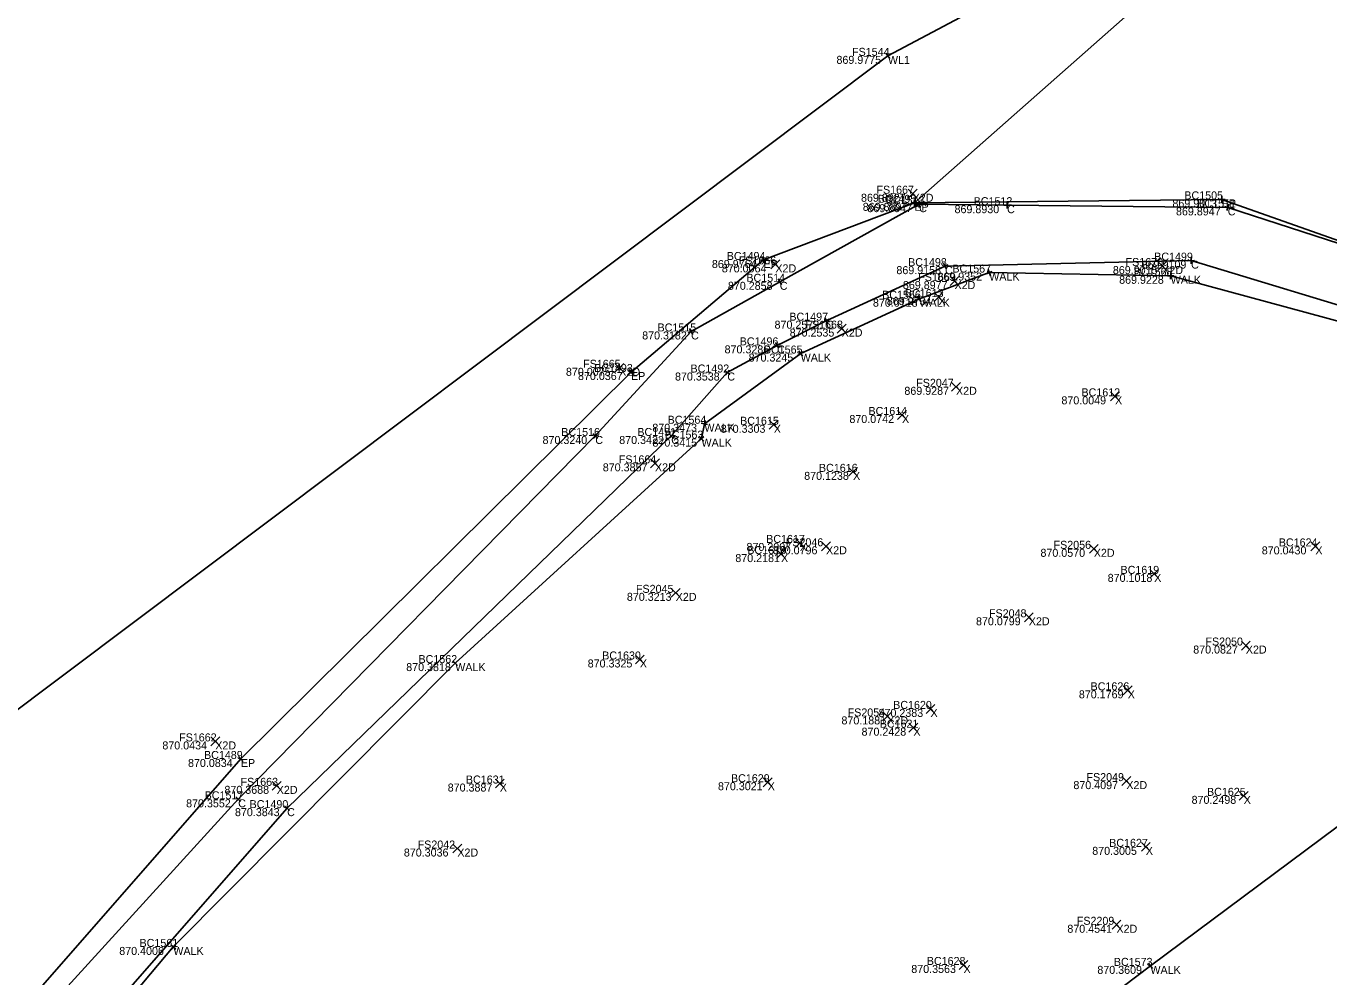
# Model space of a CAD drawing. Extents: x 1479425 to 1480294, y 379351 to 380102.
# Drawn here: x 1479701.41 to 1479711.18, y 379929 to 379936.13 of the extents above; entities that cross this region are included whole.
import ezdxf

# ---------------------------------------------------------------- set-up
doc = ezdxf.new("R2010")
doc.units = 0
for name, color, linetype in [('PV_X_Curb', 7, 'Continuous'), ('PV_X_EOP', 7, 'Continuous'), ('PV_X_Walk', 7, 'Continuous'), ('SV_X_Random_Point', 7, 'Continuous'), ('SV_X_Shot_Marker', 7, 'Continuous'), ('SV_X_Text_Comment', 7, 'Continuous'), ('SV_X_Text_Elevation', 7, 'Continuous'), ('SV_X_Text_Name', 7, 'Continuous'), ('UT_X_Water', 7, 'Continuous')]:
    doc.layers.add(name, color=color, linetype=linetype)

msp = doc.modelspace()

# ---------------------------------------------------------------- linework, layer by layer
at = {"layer": 'PV_X_Curb'}
for points in [[(1479696.2636, 379903.5386), (1479695.5705, 379906.7461), (1479695.2973, 379909.3412), (1479695.1738, 379911.6458), (1479695.3654, 379914.6115), (1479695.6976, 379917.6668), (1479696.2624, 379919.5688), (1479696.9758, 379921.5611), (1479698.1082, 379924.2136), (1479700.2799, 379927.5011), (1479703.0248, 379930.6372), (1479705.9498, 379933.539), (1479706.9435, 379934.3789), (1479708.0749, 379934.8076), (1479711.183, 379937.5526), (1479719.99, 379942.1167), (1479736.739, 379950.5318), (1479753.296, 379958.795), (1479766.716, 379965.5627), (1479785.836, 379974.8289), (1479802.25, 379983.0541), (1479831.407, 379997.252)], [(1479714.5618, 379931.5973), (1479714.9536, 379931.8464), (1479713.9233, 379933.1457), (1479712.2808, 379934.1691), (1479710.4236, 379934.7733), (1479708.7692, 379934.7899), (1479708.1103, 379934.7976), (1479707.0655, 379934.2154), (1479706.4002, 379933.8431), (1479705.6821, 379933.0592), (1479703.0049, 379930.3348), (1479700.4209, 379927.5017), (1479698.1162, 379923.7926), (1479697.0539, 379921.4468), (1479696.3167, 379919.5129), (1479695.8109, 379917.6805), (1479695.4613, 379914.2655), (1479695.2919, 379911.6604), (1479695.2827, 379911.4711), (1479695.5098, 379908.7638), (1479695.6518, 379906.8062)], [(1479696.7341, 379903.7226), (1479696.0777, 379906.871), (1479695.8572, 379909.3669), (1479695.6789, 379911.5748), (1479695.6301, 379911.7177), (1479695.7295, 379913.104), (1479695.9783, 379915.6746), (1479696.1977, 379917.4938), (1479696.6417, 379919.3847), (1479697.4123, 379921.3734), (1479698.5912, 379923.9386), (1479699.838, 379926.0575), (1479700.67, 379927.1843), (1479703.3721, 379930.2685), (1479706.2512, 379933.0593), (1479706.6718, 379933.5352), (1479707.0448, 379933.7387), (1479707.4133, 379933.9238), (1479708.304, 379934.3327), (1479710.1486, 379934.3742), (1479711.6155, 379933.9308), (1479713.6212, 379932.8847), (1479714.2993, 379932.0346), (1479714.5618, 379931.5973)]]:
    msp.add_lwpolyline(points, dxfattribs=at)
at = {"layer": 'PV_X_EOP'}
msp.add_lwpolyline([(1479708.0749, 379934.8076), (1479710.3785, 379934.8334), (1479712.1047, 379934.2215), (1479713.963, 379933.1704), (1479715.0883, 379931.8526)], dxfattribs=at)
at = {"layer": 'PV_X_Walk'}
msp.add_lwpolyline([(1479700.8191, 379927.2069), (1479702.5188, 379929.2278), (1479704.6321, 379931.3562), (1479706.478, 379933.0394), (1479706.4999, 379933.151), (1479707.2217, 379933.6773), (1479708.112, 379934.0884), (1479708.635, 379934.2846), (1479709.9955, 379934.2605), (1479711.7375, 379933.7876), (1479713.5401, 379932.634), (1479713.998, 379932.2143), (1479711.7035, 379930.4698), (1479709.8435, 379929.0857), (1479707.9993, 379927.6902), (1479707.5323, 379928.0023), (1479706.101, 379926.5176), (1479704.9058, 379925.0828), (1479704.4088, 379924.3811), (1479704.348, 379924.2805), (1479703.3879, 379922.6665), (1479702.6175, 379921.0036)], dxfattribs=at)
at = {"layer": 'SV_X_Random_Point'}
for p, q in [((1479708.0277, 379934.8423), (1479708.0943, 379934.9091)), ((1479708.0277, 379934.9091), (1479708.0943, 379934.8423)), ((1479706.9987, 379934.3127), (1479707.0653, 379934.3795)), ((1479706.9987, 379934.3795), (1479707.0653, 379934.3127)), ((1479709.8987, 379934.3), (1479709.9653, 379934.3668)), ((1479709.8987, 379934.3668), (1479709.9653, 379934.3)), ((1479708.3417, 379934.1876), (1479708.4083, 379934.2544)), ((1479708.3417, 379934.2544), (1479708.4083, 379934.1876)), ((1479708.2218, 379934.0676), (1479708.2884, 379934.1344)), ((1479708.2218, 379934.1344), (1479708.2884, 379934.0676)), ((1479707.4957, 379933.8311), (1479707.5623, 379933.8979)), ((1479707.4957, 379933.8979), (1479707.5623, 379933.8311)), ((1479705.8287, 379933.5371), (1479705.8953, 379933.6039)), ((1479705.8287, 379933.6039), (1479705.8953, 379933.5371)), ((1479708.3527, 379933.3945), (1479708.4193, 379933.4613)), ((1479708.3527, 379933.4613), (1479708.4193, 379933.3945)), ((1479709.5451, 379933.3231), (1479709.6117, 379933.3899)), ((1479709.5451, 379933.3899), (1479709.6117, 379933.3231)), ((1479707.9482, 379933.1834), (1479708.0148, 379933.2502)), ((1479707.9482, 379933.2502), (1479708.0148, 379933.1834)), ((1479706.9866, 379933.1099), (1479707.0532, 379933.1767)), ((1479706.9866, 379933.1767), (1479707.0532, 379933.1099)), ((1479706.0957, 379932.8206), (1479706.1623, 379932.8874)), ((1479706.0957, 379932.8874), (1479706.1623, 379932.8206)), ((1479707.5814, 379932.7568), (1479707.648, 379932.8236)), ((1479707.5814, 379932.8236), (1479707.648, 379932.7568)), ((1479707.1823, 379932.2238), (1479707.2489, 379932.2906)), ((1479707.1823, 379932.2906), (1479707.2489, 379932.2238)), ((1479707.3787, 379932.1988), (1479707.4453, 379932.2656)), ((1479707.3787, 379932.2656), (1479707.4453, 379932.1988)), ((1479711.0471, 379932.1979), (1479711.1137, 379932.2647)), ((1479711.0471, 379932.2647), (1479711.1137, 379932.1979)), ((1479707.0411, 379932.1403), (1479707.1077, 379932.2071)), ((1479707.0411, 379932.2071), (1479707.1077, 379932.1403)), ((1479709.3857, 379932.1797), (1479709.4523, 379932.2465)), ((1479709.3857, 379932.2465), (1479709.4523, 379932.1797)), ((1479709.8386, 379931.9918), (1479709.9052, 379932.0586)), ((1479709.8386, 379932.0586), (1479709.9052, 379931.9918)), ((1479706.2517, 379931.8496), (1479706.3183, 379931.9164)), ((1479706.2517, 379931.9164), (1479706.3183, 379931.8496)), ((1479708.8987, 379931.6664), (1479708.9653, 379931.7332)), ((1479708.8987, 379931.7332), (1479708.9653, 379931.6664)), ((1479710.5257, 379931.4543), (1479710.5923, 379931.5211)), ((1479710.5257, 379931.5211), (1479710.5923, 379931.4543)), ((1479705.9826, 379931.35), (1479706.0492, 379931.4168)), ((1479705.9826, 379931.4168), (1479706.0492, 379931.35)), ((1479709.6404, 379931.1186), (1479709.707, 379931.1854)), ((1479709.6404, 379931.1854), (1479709.707, 379931.1186)), ((1479707.8377, 379930.9229), (1479707.9043, 379930.9897)), ((1479707.8377, 379930.9897), (1479707.9043, 379930.9229)), ((1479708.1618, 379930.9792), (1479708.2284, 379931.046)), ((1479708.1618, 379931.046), (1479708.2284, 379930.9792)), ((1479708.0336, 379930.8383), (1479708.1002, 379930.9051)), ((1479708.0336, 379930.9051), (1479708.1002, 379930.8383)), ((1479702.7997, 379930.7355), (1479702.8663, 379930.8023)), ((1479702.7997, 379930.8023), (1479702.8663, 379930.7355)), ((1479706.9414, 379930.4294), (1479707.008, 379930.4962)), ((1479706.9414, 379930.4962), (1479707.008, 379930.4294)), ((1479709.6297, 379930.4378), (1479709.6963, 379930.5046)), ((1479709.6297, 379930.5046), (1479709.6963, 379930.4378)), ((1479703.2607, 379930.4024), (1479703.3273, 379930.4692)), ((1479703.2607, 379930.4692), (1479703.3273, 379930.4024)), ((1479704.9331, 379930.4196), (1479704.9997, 379930.4864)), ((1479704.9331, 379930.4864), (1479704.9997, 379930.4196)), ((1479710.5096, 379930.3273), (1479710.5762, 379930.3941)), ((1479710.5096, 379930.3941), (1479710.5762, 379930.3273)), ((1479709.7761, 379929.9449), (1479709.8427, 379930.0117)), ((1479709.7761, 379930.0117), (1479709.8427, 379929.9449)), ((1479704.6147, 379929.9323), (1479704.6813, 379929.9991)), ((1479704.6147, 379929.9991), (1479704.6813, 379929.9323)), ((1479709.5557, 379929.3605), (1479709.6223, 379929.4273)), ((1479709.5557, 379929.4273), (1479709.6223, 379929.3605)), ((1479708.4093, 379929.0592), (1479708.4759, 379929.126)), ((1479708.4093, 379929.126), (1479708.4759, 379929.0592))]:
    msp.add_line(p, q, dxfattribs=at)
at = {"layer": 'SV_X_Shot_Marker'}
for p, q in [((1479707.856, 379935.8947), (1479707.896, 379935.9247)), ((1479707.861, 379935.9297), (1479707.891, 379935.8897)), ((1479707.876, 379935.9097), (1479707.876, 379935.9097)), ((1479708.0499, 379934.8073), (1479708.0999, 379934.8079)), ((1479708.0746, 379934.8326), (1479708.0752, 379934.7826)), ((1479708.0749, 379934.8076), (1479708.0749, 379934.8076)), ((1479708.1353, 379934.7973), (1479708.0853, 379934.7979)), ((1479708.11, 379934.7726), (1479708.1106, 379934.8226)), ((1479708.1103, 379934.7976), (1479708.1103, 379934.7976)), ((1479708.7942, 379934.7896), (1479708.7442, 379934.7901)), ((1479708.7689, 379934.7649), (1479708.7694, 379934.8149)), ((1479708.7692, 379934.7899), (1479708.7692, 379934.7899)), ((1479710.3535, 379934.8331), (1479710.4035, 379934.8337)), ((1479710.3782, 379934.8584), (1479710.3788, 379934.8084)), ((1479710.3785, 379934.8334), (1479710.3785, 379934.8334)), ((1479710.4159, 379934.7495), (1479710.4313, 379934.7971)), ((1479710.4474, 379934.7656), (1479710.3998, 379934.7811)), ((1479710.4236, 379934.7733), (1479710.4236, 379934.7733)), ((1479706.9346, 379934.4023), (1479706.9524, 379934.3555)), ((1479710.148, 379934.3992), (1479710.1492, 379934.3492)), ((1479706.9201, 379934.3701), (1479706.9669, 379934.3878)), ((1479706.9435, 379934.3789), (1479706.9435, 379934.3789)), ((1479708.2813, 379934.3223), (1479708.3267, 379934.3431)), ((1479708.2936, 379934.3554), (1479708.3144, 379934.31)), ((1479708.304, 379934.3327), (1479708.304, 379934.3327)), ((1479708.6262, 379934.308), (1479708.6438, 379934.2612)), ((1479710.1236, 379934.3737), (1479710.1736, 379934.3748)), ((1479710.1486, 379934.3742), (1479710.1486, 379934.3742)), ((1479707.0873, 379934.2276), (1479707.0437, 379934.2033)), ((1479707.0777, 379934.1936), (1479707.0533, 379934.2373)), ((1479707.0655, 379934.2154), (1479707.0655, 379934.2154)), ((1479708.6116, 379934.2758), (1479708.6584, 379934.2934)), ((1479708.635, 379934.2846), (1479708.635, 379934.2846)), ((1479709.9705, 379934.261), (1479710.0205, 379934.2601)), ((1479709.9959, 379934.2855), (1479709.9951, 379934.2355)), ((1479709.9955, 379934.2605), (1479709.9955, 379934.2605)), ((1479708.1015, 379934.1111), (1479708.1225, 379934.0657)), ((1479708.0893, 379934.0779), (1479708.1347, 379934.0989)), ((1479708.112, 379934.0884), (1479708.112, 379934.0884)), ((1479707.391, 379933.9126), (1479707.4356, 379933.935)), ((1479707.4021, 379933.9462), (1479707.4245, 379933.9015)), ((1479707.4133, 379933.9238), (1479707.4133, 379933.9238)), ((1479706.422, 379933.8553), (1479706.3784, 379933.8309)), ((1479706.4124, 379933.8213), (1479706.388, 379933.8649)), ((1479706.4002, 379933.8431), (1479706.4002, 379933.8431)), ((1479707.0229, 379933.7267), (1479707.0667, 379933.7507)), ((1479707.0328, 379933.7607), (1479707.0568, 379933.7168)), ((1479707.0448, 379933.7387), (1479707.0448, 379933.7387)), ((1479707.2015, 379933.6626), (1479707.2419, 379933.692)), ((1479707.207, 379933.6975), (1479707.2364, 379933.6571)), ((1479707.2217, 379933.6773), (1479707.2217, 379933.6773)), ((1479705.9307, 379933.5229), (1479705.9689, 379933.5552)), ((1479705.9337, 379933.5581), (1479705.9659, 379933.5199)), ((1479705.9498, 379933.539), (1479705.9498, 379933.539)), ((1479706.6531, 379933.5518), (1479706.6905, 379933.5187)), ((1479706.6552, 379933.5165), (1479706.6884, 379933.554)), ((1479706.6718, 379933.5352), (1479706.6718, 379933.5352)), ((1479706.4754, 379933.1558), (1479706.5244, 379933.1462)), ((1479706.4951, 379933.1265), (1479706.5047, 379933.1756)), ((1479706.4999, 379933.151), (1479706.4999, 379933.151)), ((1479705.7005, 379933.0423), (1479705.6637, 379933.0761)), ((1479705.699, 379933.0777), (1479705.6652, 379933.0408)), ((1479705.6821, 379933.0592), (1479705.6821, 379933.0592)), ((1479706.2332, 379933.0419), (1479706.2691, 379933.0767)), ((1479706.2338, 379933.0773), (1479706.2686, 379933.0414)), ((1479706.2512, 379933.0593), (1479706.2512, 379933.0593)), ((1479706.4595, 379933.0226), (1479706.4965, 379933.0563)), ((1479706.4612, 379933.0579), (1479706.4948, 379933.0209)), ((1479706.478, 379933.0394), (1479706.478, 379933.0394)), ((1479704.6144, 379931.3738), (1479704.6498, 379931.3386)), ((1479704.6145, 379931.3385), (1479704.6497, 379931.374)), ((1479704.6321, 379931.3562), (1479704.6321, 379931.3562)), ((1479703.007, 379930.6196), (1479703.0425, 379930.6548)), ((1479703.0072, 379930.655), (1479703.0424, 379930.6195)), ((1479703.0248, 379930.6372), (1479703.0248, 379930.6372)), ((1479703.0227, 379930.3173), (1479702.9871, 379930.3523)), ((1479703.0224, 379930.3527), (1479702.9874, 379930.317)), ((1479703.0049, 379930.3348), (1479703.0049, 379930.3348)), ((1479703.3533, 379930.285), (1479703.3909, 379930.252)), ((1479703.3556, 379930.2497), (1479703.3886, 379930.2873)), ((1479703.3721, 379930.2685), (1479703.3721, 379930.2685)), ((1479702.4997, 379929.2439), (1479702.5379, 379929.2117)), ((1479702.5027, 379929.2087), (1479702.5349, 379929.247)), ((1479702.5188, 379929.2278), (1479702.5188, 379929.2278)), ((1479709.8636, 379929.1006), (1479709.8234, 379929.0708)), ((1479709.8584, 379929.0657), (1479709.8286, 379929.1058)), ((1479709.8435, 379929.0857), (1479709.8435, 379929.0857))]:
    msp.add_line(p, q, dxfattribs=at)
at = {"layer": 'UT_X_Water'}
msp.add_lwpolyline([(1479653.917, 379883.0752), (1479656.453, 379885.9011), (1479682.649, 379913.5823), (1479686.182, 379917.14), (1479686.736, 379917.6555), (1479692.788, 379923.2684), (1479699.703, 379929.7704), (1479707.876, 379935.9097), (1479714.6, 379939.4878), (1479720.618, 379942.7923), (1479734.686, 379951.003), (1479759.021, 379964.6195), (1479771.505, 379971.3041), (1479799.27, 379984.8376)], dxfattribs=at)

# ---------------------------------------------------------------- texts
at = {"layer": 'SV_X_Text_Comment'}
for s, p in [('WL1', (1479707.876, 379935.8497)), ('X2D', (1479708.061, 379934.8157)), ('EP', (1479708.0749, 379934.7476)), ('C', (1479708.1103, 379934.7376)), ('C', (1479708.7692, 379934.7299)), ('EP', (1479710.3785, 379934.7734)), ('C', (1479710.4236, 379934.7133)), ('EP', (1479706.9435, 379934.3189)), ('X2D', (1479707.032, 379934.2861)), ('C', (1479708.304, 379934.2727)), ('X2D', (1479709.932, 379934.2734)), ('C', (1479710.1486, 379934.3142)), ('C', (1479707.0655, 379934.1554)), ('X2D', (1479708.375, 379934.161)), ('WALK', (1479708.635, 379934.2246)), ('WALK', (1479709.9955, 379934.2005)), ('WALK', (1479708.112, 379934.0284)), ('X', (1479708.2551, 379934.041)), ('C', (1479707.4133, 379933.8638)), ('C', (1479706.4002, 379933.7831)), ('X2D', (1479707.529, 379933.8045)), ('C', (1479707.0448, 379933.6787)), ('WALK', (1479707.2217, 379933.6173)), ('X2D', (1479705.862, 379933.5105)), ('EP', (1479705.9498, 379933.479)), ('C', (1479706.6718, 379933.4752)), ('X2D', (1479708.386, 379933.3679)), ('X', (1479709.5784, 379933.2965)), ('WALK', (1479706.4999, 379933.091)), ('X', (1479707.0199, 379933.0833)), ('X', (1479707.9815, 379933.1568)), ('C', (1479705.6821, 379932.9992)), ('C', (1479706.2512, 379932.9993)), ('WALK', (1479706.478, 379932.9794)), ('X2D', (1479706.129, 379932.794)), ('X', (1479707.6147, 379932.7302)), ('X', (1479707.2156, 379932.1972)), ('X', (1479707.0744, 379932.1137)), ('X2D', (1479707.412, 379932.1722)), ('X2D', (1479709.419, 379932.1531)), ('X', (1479711.0804, 379932.1713)), ('X', (1479709.8719, 379931.9652)), ('X2D', (1479706.285, 379931.823)), ('X2D', (1479708.932, 379931.6398)), ('X2D', (1479710.559, 379931.4277)), ('X', (1479706.0159, 379931.3234)), ('WALK', (1479704.6321, 379931.2962)), ('X', (1479709.6737, 379931.092)), ('X', (1479708.1951, 379930.9526)), ('X2D', (1479707.871, 379930.8963)), ('X', (1479708.0669, 379930.8117)), ('X2D', (1479702.833, 379930.7089)), ('EP', (1479703.0248, 379930.5772)), ('X2D', (1479703.294, 379930.3758)), ('X', (1479704.9664, 379930.393)), ('X', (1479706.9747, 379930.4028)), ('X2D', (1479709.663, 379930.4112)), ('C', (1479703.0049, 379930.2748)), ('X', (1479710.5429, 379930.3007)), ('C', (1479703.3721, 379930.2085)), ('X2D', (1479704.648, 379929.9057)), ('X', (1479709.8094, 379929.9183)), ('X2D', (1479709.589, 379929.3339)), ('WALK', (1479702.5188, 379929.1678)), ('X', (1479708.4426, 379929.0326)), ('WALK', (1479709.8435, 379929.0257))]:
    msp.add_text(s, height=0.06, dxfattribs=at).set_placement(p)
at = {"layer": 'SV_X_Text_Elevation'}
for s, p in [('869.9775', (1479707.49, 379935.8497)), ('869.8927', (1479707.6741, 379934.8157)), ('869.8897', (1479707.687, 379934.7476)), ('869.8947', (1479707.722, 379934.7376)), ('869.8930', (1479708.3752, 379934.7299)), ('869.9013', (1479710.0086, 379934.7734)), ('869.8947', (1479710.0353, 379934.7133)), ('869.9764', (1479706.5561, 379934.3189)), ('870.0064', (1479706.6304, 379934.2861)), ('869.9158', (1479707.9393, 379934.2727)), ('869.9015', (1479709.5621, 379934.2734)), ('869.9109', (1479709.7783, 379934.3142)), ('870.2858', (1479706.6762, 379934.1554)), ('869.8977', (1479707.9881, 379934.161)), ('869.9352', (1479708.2467, 379934.2246)), ('869.9228', (1479709.6091, 379934.2005)), ('870.0118', (1479707.7634, 379934.0284)), ('869.9734', (1479707.8677, 379934.041)), ('870.2572', (1479707.0259, 379933.8638)), ('870.3182', (1479706.0336, 379933.7831)), ('870.2535', (1479707.1393, 379933.8045)), ('870.3286', (1479706.6513, 379933.6787)), ('870.3245', (1479706.8315, 379933.6173)), ('870.0075', (1479705.4619, 379933.5105)), ('870.0367', (1479705.5525, 379933.479)), ('870.3538', (1479706.2797, 379933.4752)), ('869.9287', (1479707.9991, 379933.3679)), ('870.0049', (1479709.1764, 379933.2965)), ('870.3473', (1479706.1097, 379933.091)), ('870.3303', (1479706.6226, 379933.0833)), ('870.0742', (1479707.587, 379933.1568)), ('870.3240', (1479705.2867, 379932.9992)), ('870.3422', (1479705.8615, 379932.9993)), ('870.3415', (1479706.1105, 379932.9794)), ('870.3857', (1479705.7383, 379932.794)), ('870.1238', (1479707.2481, 379932.7302)), ('870.2007', (1479706.8155, 379932.1972)), ('870.2181', (1479706.7318, 379932.1137)), ('870.0796', (1479707.0128, 379932.1722)), ('870.0570', (1479709.0193, 379932.1531)), ('870.0430', (1479710.6784, 379932.1713)), ('870.1018', (1479709.5233, 379931.9652)), ('870.3213', (1479705.9189, 379931.823)), ('870.0799', (1479708.5361, 379931.6398)), ('870.0827', (1479710.1645, 379931.4277)), ('870.3325', (1479705.6252, 379931.3234)), ('870.3818', (1479704.2646, 379931.2962)), ('870.1769', (1479709.3071, 379931.092)), ('870.2383', (1479707.8054, 379930.9526)), ('870.1881', (1479707.5275, 379930.8963)), ('870.2428', (1479707.6781, 379930.8117)), ('870.0434', (1479702.4366, 379930.7089)), ('870.0834', (1479702.6289, 379930.5772)), ('870.3688', (1479702.9019, 379930.3758)), ('870.3887', (1479704.5757, 379930.393)), ('870.3021', (1479706.6018, 379930.4028)), ('870.4097', (1479709.2662, 379930.4112)), ('870.3552', (1479702.6147, 379930.2748)), ('870.2498', (1479710.1522, 379930.3007)), ('870.3843', (1479702.9809, 379930.2085)), ('870.3036', (1479704.2469, 379929.9057)), ('870.3005', (1479709.4074, 379929.9183)), ('870.4541', (1479709.2209, 379929.3339)), ('870.4006', (1479702.1135, 379929.1678)), ('870.3563', (1479708.051, 379929.0326)), ('870.3609', (1479709.4457, 379929.0257))]:
    msp.add_text(s, height=0.06, dxfattribs=at).set_placement(p)
at = {"layer": 'SV_X_Text_Name'}
for s, p in [('FS1544', (1479707.6068, 379935.9097)), ('FS1667', (1479707.7899, 379934.8757)), ('BC1505', (1479710.0979, 379934.8334)), ('BC1495', (1479707.7986, 379934.8076)), ('BC1513', (1479707.8591, 379934.7976)), ('BC1512', (1479708.5184, 379934.7899)), ('BC1511', (1479710.1949, 379934.7733)), ('BC1494', (1479706.6676, 379934.3789)), ('FS1666', (1479706.7571, 379934.3461)), ('BC1499', (1479709.8718, 379934.3742)), ('BC1498', (1479708.0272, 379934.3327)), ('BC1567', (1479708.3591, 379934.2846)), ('FS1670', (1479709.6576, 379934.3334)), ('BC1568', (1479709.7192, 379934.2605)), ('BC1514', (1479706.8147, 379934.2154)), ('FS1669', (1479708.1034, 379934.221)), ('BC1566', (1479707.8324, 379934.0884)), ('BC1613', (1479708.0029, 379934.101)), ('BC1497', (1479707.137, 379933.9238)), ('FS1668', (1479707.2574, 379933.8645)), ('BC1515', (1479706.1489, 379933.8431)), ('BC1496', (1479706.7647, 379933.7387)), ('BC1565', (1479706.9458, 379933.6773)), ('FS1665', (1479705.5909, 379933.5705)), ('BC1493', (1479705.6735, 379933.539)), ('BC1492', (1479706.3959, 379933.5352)), ('FS2047', (1479708.0879, 379933.4279)), ('BC1612', (1479709.3267, 379933.3565)), ('BC1614', (1479707.7298, 379933.2168)), ('BC1564', (1479706.2245, 379933.151)), ('BC1615', (1479706.7677, 379933.1433)), ('BC1516', (1479705.4271, 379933.0592)), ('BC1491', (1479705.9974, 379933.0593)), ('BC1563', (1479706.2021, 379933.0394)), ('FS1664', (1479705.8583, 379932.854)), ('BC1616', (1479707.3587, 379932.7902)), ('BC1617', (1479706.9634, 379932.2572)), ('FS2046', (1479707.1101, 379932.2322)), ('FS2056', (1479709.1176, 379932.2131)), ('BC1624', (1479710.806, 379932.2313)), ('BC1618', (1479706.8217, 379932.1737)), ('BC1619', (1479709.6192, 379932.0252)), ('FS2045', (1479705.9869, 379931.883)), ('FS2048', (1479708.6334, 379931.6998)), ('FS2050', (1479710.2562, 379931.4877)), ('BC1562', (1479704.3567, 379931.3562)), ('BC1630', (1479705.7339, 379931.3834)), ('BC1626', (1479709.395, 379931.152)), ('FS2054', (1479707.5739, 379930.9563)), ('BC1620', (1479707.915, 379931.0126)), ('BC1621', (1479707.8145, 379930.8717)), ('FS1662', (1479702.5623, 379930.7689)), ('BC1489', (1479702.7489, 379930.6372)), ('FS1663', (1479703.0229, 379930.4358)), ('BC1631', (1479704.7122, 379930.453)), ('BC1629', (1479706.6993, 379930.4628)), ('FS2049', (1479709.3644, 379930.4712)), ('BC1517', (1479702.7536, 379930.3348)), ('BC1625', (1479710.268, 379930.3607)), ('BC1490', (1479703.0906, 379930.2685)), ('FS2042', (1479704.3504, 379929.9657)), ('BC1627', (1479709.5345, 379929.9783)), ('FS2209', (1479709.2919, 379929.3939)), ('BC1561', (1479702.2655, 379929.2278)), ('BC1628', (1479708.1672, 379929.0926)), ('BC1573', (1479709.5695, 379929.0857))]:
    msp.add_text(s, height=0.06, dxfattribs=at).set_placement(p)

doc.saveas('drawing.dxf')
